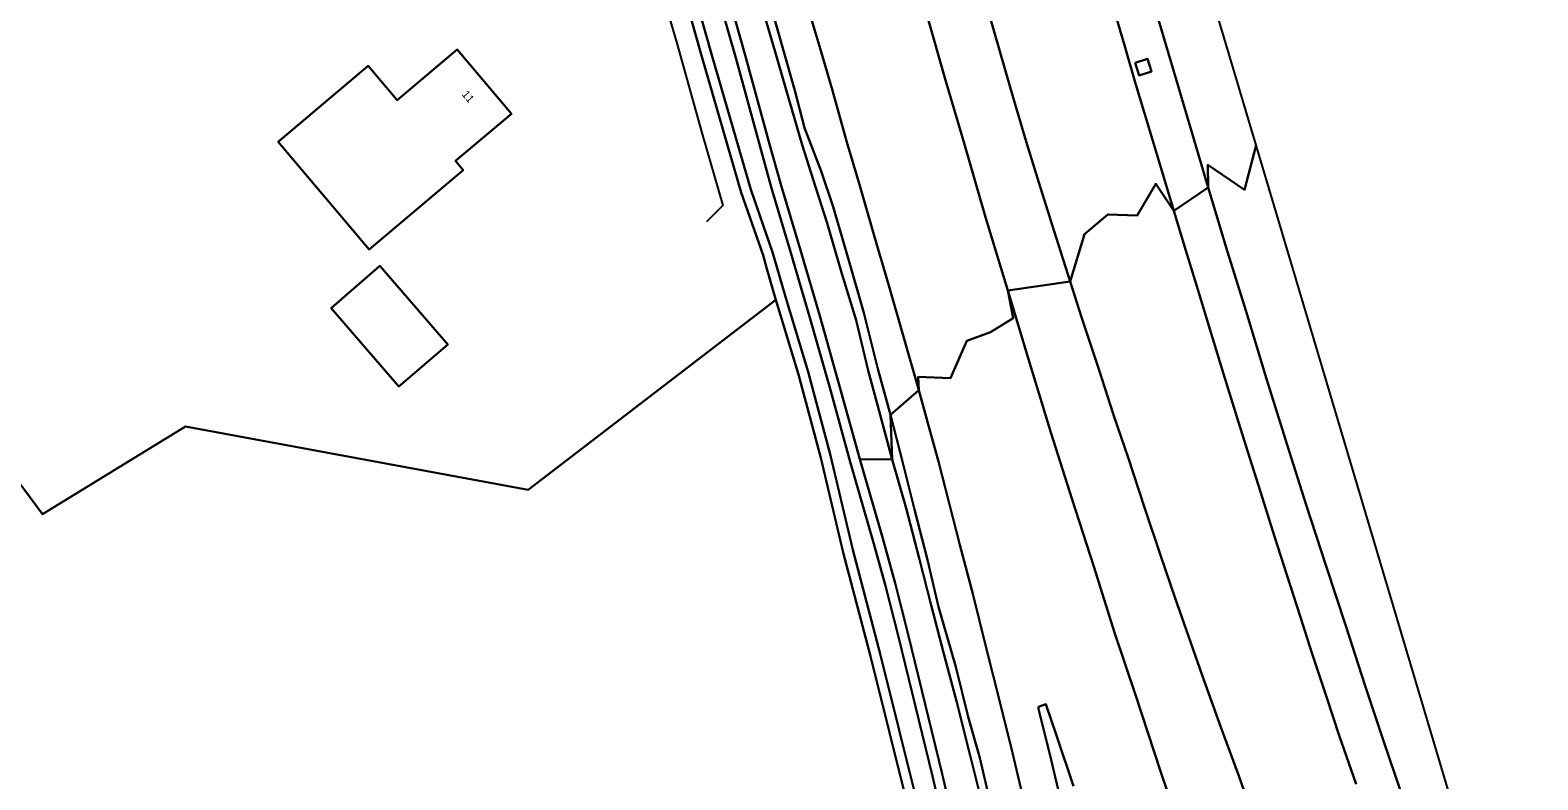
# Model space of a CAD drawing. Extents: x 155209 to 156748, y 385356 to 388487.
# Drawn here: x 156219 to 156410.1, y 385935.1 to 386030.1 of the extents above; entities that cross this region are included whole.
import ezdxf

# ---------------------------------------------------------------- set-up
doc = ezdxf.new("R2010")
doc.units = 0
for name, color, linetype in [('IMGEO_Berm_groen', 7, 'Continuous'), ('IMGEO_Erf', 7, 'Continuous'), ('IMGEO_Grasland_agrarisch', 7, 'Continuous'), ('IMGEO_Grasland_overig', 7, 'Continuous'), ('IMGEO_Muur', 7, 'Continuous'), ('IMGEO_Oever', 7, 'Continuous'), ('IMGEO_Pand', 7, 'Continuous'), ('IMGEO_Pand_nummerreeks', 7, 'Continuous'), ('IMGEO_Rijbaan_autosnelweg', 7, 'Continuous'), ('IMGEO_Rijbaan_autoweg', 7, 'Continuous'), ('IMGEO_Terreindeel_gesloten', 7, 'Continuous'), ('IMGEO_Waterloop', 7, 'Continuous')]:
    doc.layers.add(name, color=color, linetype=linetype)

msp = doc.modelspace()

# ---------------------------------------------------------------- linework, layer by layer
at = {"layer": 'IMGEO_Berm_groen'}
for points in [[(156311.45, 386034.14), (156313.45, 386027.35), (156315.21, 386021.23), (156316.84, 386015.57), (156318.25, 386011.17), (156320.02, 386005.64), (156321.86, 385999.37), (156323.71, 385993.33), (156325.24, 385986.98), (156326.76, 385981.33), (156328.27, 385975.67), (156328.07, 385981.35), (156326.46, 385987.2), (156324.68, 385994.26), (156322.78, 386000.9), (156320.8, 386007.69), (156319.26, 386012.25), (156317.17, 386017.73), (156315.93, 386022.46), (156314.45, 386027.66), (156312.54, 386034.39)], [(156312.54, 386034.39), (156314.45, 386027.66), (156315.93, 386022.46), (156317.17, 386017.73), (156319.26, 386012.25), (156320.8, 386007.69), (156322.78, 386000.9), (156324.68, 385994.26), (156326.46, 385987.2), (156328.07, 385981.35), (156331.64, 385984.47), (156329.68, 385991.39), (156327.84, 385997.73), (156326.05, 386003.89), (156324.23, 386010.26), (156322.54, 386015.92), (156320.69, 386022.45), (156319.05, 386028.06), (156317.29, 386034.03)], [(156332.69, 386031.91), (156335.05, 386023.78), (156337.39, 386015.76), (156340.1, 386006.42), (156342.93, 385997.09), (156350.82, 385998.26), (156348.47, 386005.67), (156346.86, 386010.78), (156345.26, 386016.01), (156343.62, 386021.58), (156341.96, 386027.27), (156340.17, 386033.42)], [(156356.01, 386034.1), (156357.74, 386028.21), (156359.13, 386023.36), (156360.76, 386017.9), (156362.39, 386012.55), (156363.99, 386007.19), (156368.34, 386010.18), (156365.86, 386018.43), (156363.64, 386026), (156361.5, 386033.27)], [(156393.35, 385931.83), (156390.64, 385939.77), (156388.24, 385947.01), (156385.73, 385954.75), (156383.34, 385962.03), (156380.72, 385970.09), (156378.39, 385977.41), (156375.73, 385985.9), (156373.14, 385994.43), (156370.78, 386002.02), (156368.34, 386010.18), (156363.99, 386007.19), (156365.51, 386002.18), (156367.01, 385997.25), (156368.58, 385992.1), (156370.28, 385986.53), (156372.16, 385980.41), (156373.61, 385975.87), (156374.95, 385971.57), (156376.74, 385965.93), (156378.33, 385960.96), (156379.98, 385955.82), (156381.51, 385951.05), (156383.32, 385945.6), (156384.95, 385940.71), (156387.08, 385934.56)], [(156374.02, 385930.39), (156372.22, 385935.59), (156369.92, 385941.75), (156367.62, 385948.22), (156365.53, 385954.13), (156364.16, 385958.1), (156362.3, 385963.57), (156360.27, 385969.61), (156358.18, 385975.96), (156356.39, 385981.22), (156354.46, 385987.14), (156352.31, 385993.61), (156350.82, 385998.26), (156342.93, 385997.09), (156345.55, 385988.42), (156348.44, 385978.98), (156351.05, 385970.73), (156353.82, 385962.14), (156356.46, 385953.75), (156359.13, 385945.86), (156362.3, 385936.17), (156365.36, 385927.05)], [(156344.95, 385932.45), (156343.54, 385938.5), (156341.9, 385944.97), (156340.24, 385951.66), (156338.48, 385958.65), (156336.85, 385964.86), (156335.51, 385970.14), (156334.15, 385975.44), (156333, 385979.55), (156331.64, 385984.47), (156328.07, 385981.35), (156329.6, 385975.27), (156331.1, 385969.34), (156332.73, 385962.99), (156334.14, 385957), (156336.32, 385949.43), (156337.91, 385943.08), (156339.4, 385937.89), (156340.93, 385931.15)], [(156351.25, 385934.28), (156349.06, 385940.84), (156347.75, 385944.67), (156346.83, 385944.33), (156346.82, 385944.08), (156348.41, 385937.62), (156350.88, 385927.24)]]:
    msp.add_lwpolyline(points, dxfattribs=at)
msp.add_lwpolyline([(156359.07, 386025.96), (156360.63, 386026.47), (156361.15, 386024.87), (156359.58, 386024.37)], close=True, dxfattribs=at)
at = {"layer": 'IMGEO_Erf'}
msp.add_lwpolyline([(156185.49, 386016.08), (156220.55, 385968.74), (156238.7, 385979.88), (156282.13, 385971.86), (156313.52, 385995.94), (156312.39, 385999.87), (156311.9, 386001.59), (156309.14, 386009.51), (156304.19, 386026.59), (156301.15, 386037.36)], dxfattribs=at)
for points in [[(156273.12, 386027.63), (156279.99, 386019.51), (156272.91, 386013.52), (156273.88, 386012.37), (156270.07, 386009.14), (156261.98, 386002.3), (156250.44, 386015.94), (156258.02, 386022.35), (156261.84, 386025.58), (156265.53, 386021.21)], [(156257.14, 385994.88), (156263.34, 386000.22), (156271.92, 385990.25), (156265.72, 385984.92)]]:
    msp.add_lwpolyline(points, close=True, dxfattribs=at)
at = {"layer": 'IMGEO_Grasland_agrarisch'}
msp.add_lwpolyline([(156330.36, 385931.41), (156325.53, 385950.77), (156322.07, 385963.91), (156319.21, 385975.88), (156316.41, 385986.45), (156313.52, 385995.94), (156282.13, 385971.86), (156238.7, 385979.88), (156220.55, 385968.74), (156185.49, 386016.08)], dxfattribs=at)
at = {"layer": 'IMGEO_Grasland_overig'}
for points in [[(156307.08, 386035.94), (156309.64, 386026.95), (156312.73, 386015.64), (156314.19, 386010.42), (156316.65, 386002.24), (156319.09, 385993.88), (156321.69, 385984.67), (156324.17, 385975.73), (156328.27, 385975.67), (156326.76, 385981.33), (156325.24, 385986.98), (156323.71, 385993.33), (156321.86, 385999.37), (156320.02, 386005.64), (156318.25, 386011.17), (156316.84, 386015.57), (156315.21, 386021.23), (156313.45, 386027.35), (156311.45, 386034.14)], [(156340.93, 385931.15), (156339.4, 385937.89), (156337.91, 385943.08), (156336.32, 385949.43), (156334.14, 385957), (156332.73, 385962.99), (156331.1, 385969.34), (156329.6, 385975.27), (156328.07, 385981.35), (156328.27, 385975.67), (156330.06, 385969.5), (156331.68, 385963.19), (156333.2, 385957.24), (156334.76, 385951.24), (156336.41, 385945.08), (156338.18, 385938), (156339.63, 385932.28)], [(156339.63, 385932.28), (156338.18, 385938), (156336.41, 385945.08), (156334.76, 385951.24), (156333.2, 385957.24), (156331.68, 385963.19), (156330.06, 385969.5), (156328.27, 385975.67), (156324.17, 385975.73), (156327.09, 385965.66), (156328.66, 385960), (156330.31, 385953.51), (156334.61, 385935.86), (156337.1, 385925.1)]]:
    msp.add_lwpolyline(points, dxfattribs=at)
at = {"layer": 'IMGEO_Muur'}
msp.add_lwpolyline([(156292.87, 386056.7), (156297.31, 386041.04), (156300.99, 386028.46), (156304.14, 386017.08), (156306.82, 386007.87), (156304.75, 386005.81)], dxfattribs=at)
at = {"layer": 'IMGEO_Oever'}
for points in [[(156301.15, 386037.36), (156304.19, 386026.59), (156309.14, 386009.51), (156311.9, 386001.59), (156312.39, 385999.87), (156313.52, 385995.94), (156316.41, 385986.45), (156319.21, 385975.88), (156322.07, 385963.91), (156325.53, 385950.77), (156330.36, 385931.41)], [(156331.58, 385931.7), (156326.75, 385951.08), (156323.29, 385964.22), (156320.43, 385976.19), (156317.62, 385986.79), (156314.73, 385996.29), (156313.6, 386000.22), (156313.1, 386001.97), (156310.34, 386009.9), (156305.39, 386026.93), (156302.36, 386037.71)], [(156305.88, 386035.59), (156308.43, 386026.61), (156311.52, 386015.31), (156312.98, 386010.07), (156315.44, 386001.88), (156317.88, 385993.53), (156320.48, 385984.34), (156322.96, 385975.39), (156325.88, 385965.31), (156327.44, 385959.67), (156329.09, 385953.21), (156333.39, 385935.57), (156335.87, 385924.83)], [(156337.1, 385925.1), (156334.61, 385935.86), (156330.31, 385953.51), (156328.66, 385960), (156327.09, 385965.66), (156324.17, 385975.73), (156321.69, 385984.67), (156319.09, 385993.88), (156316.65, 386002.24), (156314.19, 386010.42), (156312.73, 386015.64), (156309.64, 386026.95), (156307.08, 386035.94)]]:
    msp.add_lwpolyline(points, dxfattribs=at)
at = {"layer": 'IMGEO_Pand'}
for points in [[(156270.07, 386009.14), (156273.88, 386012.37), (156272.91, 386013.52), (156279.99, 386019.51), (156273.12, 386027.63), (156265.53, 386021.21), (156261.84, 386025.58), (156258.02, 386022.35), (156250.44, 386015.94), (156261.98, 386002.3)], [(156265.72, 385984.92), (156271.92, 385990.25), (156263.34, 386000.22), (156257.14, 385994.88)]]:
    msp.add_lwpolyline(points, close=True, dxfattribs=at)
at = {"layer": 'IMGEO_Rijbaan_autosnelweg'}
for points in [[(156361.5, 386033.27), (156363.64, 386026), (156365.86, 386018.43), (156368.34, 386010.18), (156368.28, 386013.02), (156372.95, 386009.85), (156374.41, 386015.53), (156347.46, 386105.98)], [(156340.17, 386033.42), (156341.96, 386027.27), (156343.62, 386021.58), (156345.26, 386016.01), (156346.86, 386010.78), (156348.47, 386005.67), (156350.82, 385998.26), (156352.65, 386004.23), (156355.63, 386006.76), (156359.31, 386006.63), (156361.69, 386010.61), (156363.99, 386007.19), (156362.39, 386012.55), (156360.76, 386017.9), (156359.13, 386023.36), (156357.74, 386028.21), (156356.01, 386034.1)], [(156410.12, 385895.62), (156374.41, 386015.53), (156372.95, 386009.85), (156368.28, 386013.02), (156368.34, 386010.18), (156370.78, 386002.02), (156373.14, 385994.43), (156375.73, 385985.9), (156378.39, 385977.41), (156380.72, 385970.09), (156383.34, 385962.03), (156385.73, 385954.75), (156388.24, 385947.01), (156390.64, 385939.77), (156393.35, 385931.83)], [(156387.08, 385934.56), (156384.95, 385940.71), (156383.32, 385945.6), (156381.51, 385951.05), (156379.98, 385955.82), (156378.33, 385960.96), (156376.74, 385965.93), (156374.95, 385971.57), (156373.61, 385975.87), (156372.16, 385980.41), (156370.28, 385986.53), (156368.58, 385992.1), (156367.01, 385997.25), (156365.51, 386002.18), (156363.99, 386007.19), (156361.69, 386010.61), (156359.31, 386006.63), (156355.63, 386006.76), (156352.65, 386004.23), (156350.82, 385998.26), (156352.31, 385993.61), (156354.46, 385987.14), (156356.39, 385981.22), (156358.18, 385975.96), (156360.27, 385969.61), (156362.3, 385963.57), (156364.16, 385958.1), (156365.53, 385954.13), (156367.62, 385948.22), (156369.92, 385941.75), (156372.22, 385935.59), (156374.02, 385930.39)]]:
    msp.add_lwpolyline(points, dxfattribs=at)
at = {"layer": 'IMGEO_Rijbaan_autoweg'}
for points in [[(156317.29, 386034.03), (156319.05, 386028.06), (156320.69, 386022.45), (156322.54, 386015.92), (156324.23, 386010.26), (156326.05, 386003.89), (156327.84, 385997.73), (156329.68, 385991.39), (156331.64, 385984.47), (156331.56, 385986.16), (156335.65, 385985.99), (156337.72, 385990.71), (156340.75, 385991.83), (156343.61, 385993.62), (156342.93, 385997.09), (156340.1, 386006.42), (156337.39, 386015.76), (156335.05, 386023.78), (156332.69, 386031.91)], [(156365.36, 385927.05), (156362.3, 385936.17), (156359.13, 385945.86), (156356.46, 385953.75), (156353.82, 385962.14), (156351.05, 385970.73), (156348.44, 385978.98), (156345.55, 385988.42), (156342.93, 385997.09), (156343.61, 385993.62), (156340.75, 385991.83), (156337.72, 385990.71), (156335.65, 385985.99), (156331.56, 385986.16), (156331.64, 385984.47), (156333, 385979.55), (156334.15, 385975.44), (156335.51, 385970.14), (156336.85, 385964.86), (156338.48, 385958.65), (156340.24, 385951.66), (156341.9, 385944.97), (156343.54, 385938.5), (156344.95, 385932.45)], [(156350.88, 385927.24), (156348.41, 385937.62), (156346.82, 385944.08), (156346.83, 385944.33), (156347.75, 385944.67), (156349.06, 385940.84), (156351.25, 385934.28)]]:
    msp.add_lwpolyline(points, dxfattribs=at)
at = {"layer": 'IMGEO_Terreindeel_gesloten'}
msp.add_lwpolyline([(156359.07, 386025.96), (156359.58, 386024.37), (156361.15, 386024.87), (156360.63, 386026.47)], close=True, dxfattribs=at)
at = {"layer": 'IMGEO_Waterloop'}
for points in [[(156302.36, 386037.71), (156305.39, 386026.93), (156310.34, 386009.9), (156313.1, 386001.97), (156313.6, 386000.22), (156314.73, 385996.29), (156317.62, 385986.79), (156320.43, 385976.19), (156323.29, 385964.22), (156326.75, 385951.08), (156331.58, 385931.7)], [(156335.87, 385924.83), (156333.39, 385935.57), (156329.09, 385953.21), (156327.44, 385959.67), (156325.88, 385965.31), (156322.96, 385975.39), (156320.48, 385984.34), (156317.88, 385993.53), (156315.44, 386001.88), (156312.98, 386010.07), (156311.52, 386015.31), (156308.43, 386026.61), (156305.88, 386035.59)]]:
    msp.add_lwpolyline(points, dxfattribs=at)

# ---------------------------------------------------------------- texts
at = {"layer": 'IMGEO_Pand_nummerreeks'}
msp.add_text('11', height=1, rotation=310.2063, dxfattribs=at).set_placement((156273.65, 386021.93))

doc.saveas('drawing.dxf')
